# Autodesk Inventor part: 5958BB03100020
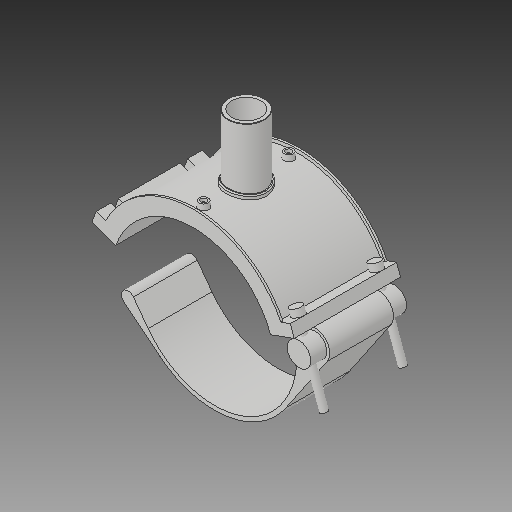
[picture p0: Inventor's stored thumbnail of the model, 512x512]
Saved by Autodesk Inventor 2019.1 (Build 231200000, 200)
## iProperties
Created: 2017-07
Part Number: 5958BB03100020
Material: Generic
Description: PLASSON BRANCH SADDLE 10'' x 2''
Document SubType Name: Modeling
Designer: KIM
Mass: 764.267 g
Surface Area: 1930.38 cm^2
Volume: 764.267 cm^3
Density: 1 g/cm^3
Appearance: Default
Author: KIM
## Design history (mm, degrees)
derived "5958B.ipt"
feature "Solid1::5958B.ipt"
feature "Solid2::5958B.ipt"
feature "Solid3::5958B.ipt"
tag "TaggingFeature1"
body "Solid1"
body "Solid2"
body "Solid3"
other parameters: "d0" = 272.7, "d2" = 234.7722, "d3" = 68.175, "d4" = 176.022, "d5" = 0, "d6" = 0.1, "d8" = 0, "d19" = 6, "d20" = 6, "d21" = 105.6132, "d23" = 0, "d24" = 52.8066, "d26" = 0, "d27" = 3, "d28" = 3, "d29" = 3, "d30" = 90.9, "d31" = 6, "d32" = 0, "d33" = 0, "d34" = 0.6, "d40" = 163.46512, "d41" = 66.11, "d43" = 0, "d45" = 0, "d47" = 262.08, "d48" = 60.1, "d50" = 0, "d70" = 15, "d72" = 0, "d73" = 6, "d75" = 5, "d76" = 0, "d77" = 13.635, "d78" = 166.35, "d79" = 15, "d80" = 70.4088, "d82" = 5 deg, "d84" = 4, "d85" = 14, "d86" = 0, "d87" = 3, "d88" = 0, "d89" = 1, "d90" = 1, "d91" = 140.8176, "d92" = 0, "d93" = 0.5, "d94" = 143.52632, "d96" = 320.64312, "d97" = 3.52044, "d98" = 0, "d102" = 1.803, "d103" = 48.08, "d105" = 0, "d109" = -34.96733, "d117" = 0.601, "d120" = 140 deg, "d121" = 24.228, "d122" = 20 deg, "d123" = 628.712, "d124" = 188.6136, "d126" = 0, "d143" = 286.335, "d150" = 49.086, "d159" = 8.3312, "d161" = 6.8175, "d162" = 105.6132, "d163" = 0, "d167" = 54.54, "d168" = 142.88909, "d173" = 1, "d175" = 136.35, "d176" = 20 deg, "d177" = 19.089, "d178" = 41.656, "d180" = 0, "d185" = 57.20715, "d186" = 57.20715, "d187" = 157.178, "d188" = 12.4968, "d189" = 19.089, "d190" = 0, "d191" = 235.767, "d200" = 20.828, "d202" = 0, "d216" = 158.4198, "d217" = 0, "d221" = 65.12814, "d222" = 19.089, "d223" = 11.4534, "d224" = 136.35, "d225" = 11.4534, "d227" = 39.2688, "d230" = 166.347, "d236" = 11.5 deg, "d238" = 20 deg, "d239" = 19.089, "d240" = 3.52044, "d241" = 0, "d242" = 5.454, "d_" = 272.7, "B_" = 180.594, "H_" = 104.902, "L_" = 176.022, "d_t" = 6, "d_1" = 60.1, "H_1" = 84.074, "d1" = 314.356, "d148" = 6.8175, "d160" = 6.8175
